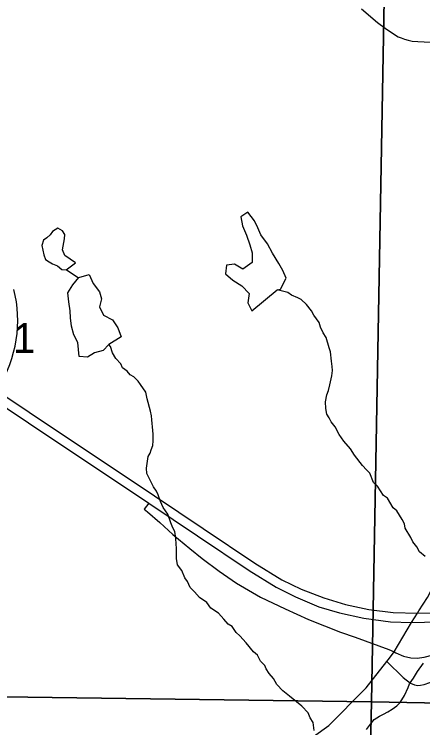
# Model space of a CAD drawing. Extents: x 0 to 34, y 0 to 22.
# Drawn here: x 3.401 to 3.978, y 16.77 to 17.776 of the extents above; entities that cross this region are included whole.
import ezdxf

# ---------------------------------------------------------------- set-up
doc = ezdxf.new("R2010")
doc.units = 0
for name, color, linetype in [('GM_X_County_Road', 7, 'Continuous'), ('GM_X_Interchange_Ramps', 7, 'Continuous'), ('GM_X_Interstate_Route', 7, 'Continuous'), ('GM_X_Interstate_Shield', 7, 'Continuous'), ('GM_X_Minor_Lake', 7, 'Continuous'), ('GM_X_Minor_River', 7, 'Continuous'), ('GM_X_Section', 7, 'Continuous'), ('GM_X_Section_Text', 7, 'Continuous'), ('GM_X_State_Route', 7, 'Continuous'), ('GM_X_Township_Road', 7, 'Continuous'), ('GM_X_US_Route', 7, 'Continuous')]:
    doc.layers.add(name, color=color, linetype=linetype)

msp = doc.modelspace()

# ---------------------------------------------------------------- linework, layer by layer
at = {"layer": 'GM_X_County_Road'}
msp.add_lwpolyline([(3.891, 17.7836), (3.9137, 17.7643), (3.9245, 17.756), (3.9335, 17.7499), (3.9431, 17.7441), (3.947, 17.7425), (3.9517, 17.7407), (3.9569, 17.7392), (3.9628, 17.738), (3.9706, 17.7373), (3.9979, 17.7358)], dxfattribs=at)
at = {"layer": 'GM_X_Interchange_Ramps'}
for points in [[(3.5913, 17.0864), (3.5849, 17.0781), (3.5894, 17.0742), (3.6067, 17.0592), (3.6253, 17.0424), (3.6492, 17.0225), (3.6666, 17.0086), (3.6904, 16.9908), (3.7151, 16.9737), (3.7489, 16.954), (3.7836, 16.9377), (3.8166, 16.9228), (3.8614, 16.905), (3.8821, 16.8975)], [(3.9374, 16.8771), (3.9398, 16.8758), (3.9505, 16.8707), (3.9607, 16.8684), (3.9698, 16.8683), (3.9796, 16.8695), (3.9921, 16.8727), (4.0041, 16.8782), (4.0566, 16.9039), (4.1192, 16.9366), (4.1254, 16.9397), (4.1215, 16.9477)], [(3.8821, 16.8975), (3.9296, 16.8803), (3.9374, 16.8771)]]:
    msp.add_lwpolyline(points, dxfattribs=at)
at = {"layer": 'GM_X_Interstate_Route'}
for points in [[(2.8343, 17.6093), (3.4225, 17.2149), (3.5995, 17.097), (3.6679, 17.051), (3.741, 17.0021), (3.7789, 16.9786), (3.8063, 16.9653), (3.8379, 16.9533), (3.8686, 16.9439), (3.9015, 16.9368), (3.936, 16.9325), (3.9703, 16.9317), (3.9919, 16.9322), (4.0072, 16.9333), (4.0421, 16.9388), (4.0807, 16.9496), (4.1185, 16.9639), (4.1778, 16.99), (4.2466, 17.0247)], [(3.0829, 17.427), (3.4215, 17.1997), (3.5913, 17.0864)], [(3.5913, 17.0864), (3.6597, 17.0405), (3.7327, 16.9916), (3.7707, 16.9681), (3.7981, 16.9547), (3.8312, 16.9407), (3.8604, 16.9319), (3.8946, 16.9245), (3.9319, 16.9192), (3.9616, 16.9183), (3.9985, 16.9192), (4.0407, 16.9251), (4.0872, 16.9354), (4.1215, 16.9477)]]:
    msp.add_lwpolyline(points, dxfattribs=at)
at = {"layer": 'GM_X_Interstate_Shield'}
msp.add_arc((3.2288, 17.3445), 0.1776, 281.537, 14.1934, dxfattribs=at)
at = {"layer": 'GM_X_Minor_Lake'}
msp.add_line((3.7366, 17.3579), (3.7725, 17.3873), dxfattribs=at)
for points in [[(3.7725, 17.3873), (3.7769, 17.3883), (3.7849, 17.4037), (3.7803, 17.4145), (3.7748, 17.4245), (3.7657, 17.4392), (3.7588, 17.4523), (3.7493, 17.4651), (3.745, 17.4747), (3.7403, 17.4847), (3.7311, 17.4967), (3.7211, 17.4901), (3.7234, 17.4775), (3.7288, 17.4645), (3.7337, 17.4507), (3.7372, 17.4395), (3.7369, 17.4259), (3.7237, 17.4163), (3.7121, 17.4235), (3.701, 17.4223), (3.6996, 17.4098), (3.7096, 17.4011), (3.7223, 17.3932), (3.7327, 17.3823), (3.7308, 17.369), (3.7366, 17.3579)], [(3.4748, 17.4157), (3.488, 17.4252), (3.473, 17.4359), (3.4694, 17.4436), (3.4725, 17.4591), (3.4727, 17.4655), (3.4694, 17.4706), (3.4627, 17.4745), (3.4553, 17.4698), (3.4522, 17.4649), (3.4475, 17.4605), (3.4428, 17.4576), (3.4404, 17.45), (3.443, 17.4367), (3.4455, 17.4301), (3.4508, 17.4266), (3.4556, 17.4242), (3.4624, 17.4213)], [(3.4624, 17.4213), (3.4687, 17.4159), (3.4748, 17.4157)], [(3.5347, 17.3105), (3.5269, 17.3018), (3.5146, 17.2987), (3.505, 17.2925), (3.4932, 17.2936), (3.4919, 17.3031), (3.4911, 17.313), (3.4857, 17.3238), (3.4822, 17.3361), (3.481, 17.3479), (3.4801, 17.3578), (3.4785, 17.3704), (3.477, 17.3833), (3.4841, 17.3942), (3.4927, 17.4046), (3.5073, 17.4091), (3.5126, 17.3961), (3.5218, 17.3844), (3.5246, 17.3745), (3.5217, 17.3632), (3.5274, 17.3516), (3.5398, 17.3452), (3.5475, 17.3336)], [(3.5475, 17.3336), (3.5523, 17.3211), (3.5347, 17.3105)]]:
    msp.add_lwpolyline(points, dxfattribs=at)
at = {"layer": 'GM_X_Minor_River'}
for points in [[(3.4921, 17.4039), (3.4748, 17.4157)], [(3.9812, 17.0112), (3.9731, 17.0179), (3.9692, 17.0249), (3.9637, 17.0319), (3.9609, 17.0381), (3.953, 17.0516), (3.9517, 17.0574), (3.9485, 17.0636), (3.9413, 17.0756), (3.9361, 17.08), (3.9279, 17.0935), (3.9223, 17.0972), (3.9137, 17.1108), (3.9081, 17.1159), (3.9029, 17.129), (3.8981, 17.1337), (3.8926, 17.1396), (3.8814, 17.1544), (3.8756, 17.163), (3.8661, 17.174), (3.8596, 17.1833), (3.8543, 17.1941), (3.8484, 17.2012), (3.8456, 17.207), (3.8424, 17.212), (3.8411, 17.22), (3.8403, 17.2296), (3.8422, 17.2394), (3.8447, 17.2454), (3.8464, 17.2533), (3.8495, 17.2661), (3.8502, 17.2737), (3.85, 17.2794), (3.8488, 17.287), (3.8473, 17.3), (3.8456, 17.3054), (3.8412, 17.32), (3.8372, 17.3266), (3.8333, 17.3347), (3.8313, 17.3412), (3.824, 17.3517), (3.8208, 17.3579), (3.8135, 17.3665), (3.8062, 17.3736), (3.8013, 17.3761), (3.7927, 17.3798), (3.7872, 17.3834), (3.7725, 17.3873)], [(3.8247, 16.7662), (3.8232, 16.7776), (3.8189, 16.7842), (3.8161, 16.7912), (3.8073, 16.8006), (3.7899, 16.8145), (3.7803, 16.822), (3.7719, 16.8311), (3.7673, 16.8396), (3.761, 16.8466), (3.7567, 16.8529), (3.755, 16.8579), (3.7487, 16.8641), (3.7445, 16.8723), (3.7389, 16.877), (3.7287, 16.8899), (3.7196, 16.8994), (3.7144, 16.9045), (3.7086, 16.9126), (3.7034, 16.9159), (3.6972, 16.9233), (3.6896, 16.9315), (3.6788, 16.9388), (3.673, 16.9466), (3.6626, 16.9538), (3.6557, 16.9616), (3.6498, 16.9679), (3.6459, 16.9764), (3.6419, 16.9814), (3.6377, 16.9918), (3.6315, 16.9997), (3.6303, 17.0088), (3.6302, 17.0168), (3.6304, 17.0225), (3.6299, 17.0294), (3.6294, 17.037), (3.6278, 17.0465), (3.625, 17.0519), (3.6222, 17.0589), (3.6181, 17.0712), (3.6115, 17.0805), (3.6077, 17.089), (3.6046, 17.0986), (3.6021, 17.1037), (3.5977, 17.1095), (3.5924, 17.1211), (3.5885, 17.1284), (3.588, 17.1361), (3.5901, 17.1523), (3.5933, 17.1572), (3.5946, 17.162), (3.5967, 17.1677), (3.5973, 17.1745), (3.5973, 17.184), (3.5971, 17.1889), (3.5953, 17.2042), (3.5951, 17.2095), (3.5938, 17.2164), (3.5891, 17.2337), (3.5872, 17.2429), (3.5796, 17.2538), (3.5763, 17.2588), (3.5701, 17.2647), (3.5648, 17.2676), (3.5608, 17.2727), (3.5542, 17.2774), (3.5517, 17.2829), (3.5448, 17.2907), (3.5401, 17.2985), (3.537, 17.3073), (3.5347, 17.3105)], [(3.8984, 16.7674), (3.904, 16.7752), (3.9091, 16.7815), (3.9165, 16.7862), (3.9223, 16.789), (3.9285, 16.7926), (3.9343, 16.7962), (3.9413, 16.8009), (3.946, 16.8057), (3.9517, 16.8157), (3.957, 16.8269), (3.9587, 16.8318), (3.9647, 16.84), (3.97, 16.8493), (3.9787, 16.8612)]]:
    msp.add_lwpolyline(points, dxfattribs=at)
at = {"layer": 'GM_X_Section'}
for points in [[(3.923, 17.7965), (3.9054, 16.8066), (2.9007, 16.8204), (2.9334, 17.8114)], [(3.9054, 16.8066), (4.328, 16.7986), (4.3256, 16.7771), (4.3103, 16.7385), (4.3, 16.7205), (4.2802, 16.7024), (4.2517, 16.6823), (4.2355, 16.6713), (4.2093, 16.6549), (4.1675, 16.6328), (4.1258, 16.6145), (4.0845, 16.5985), (4.0692, 16.5947), (4.0556, 16.5931), (4.0495, 16.5944), (4.0387, 16.6015), (4.0223, 16.614), (4.0029, 16.6235), (3.9905, 16.6288), (3.9622, 16.6321), (3.9299, 16.6291), (3.9079, 16.6163), (3.9011, 16.6124)]]:
    msp.add_lwpolyline(points, close=True, dxfattribs=at)
for points in [[(4.328, 16.7986), (3.9054, 16.8066), (3.923, 17.7965)], [(2.9007, 16.8204), (3.9054, 16.8066), (3.9011, 16.6124), (3.88, 16.6356), (3.8496, 16.6451), (3.806, 16.6427), (3.7481, 16.632), (3.6889, 16.6111), (3.6323, 16.5909), (3.6125, 16.5868), (3.5393, 16.5662), (3.511, 16.5548), (3.4795, 16.5389), (3.4415, 16.5156), (3.3921, 16.48)]]:
    msp.add_lwpolyline(points, dxfattribs=at)
at = {"layer": 'GM_X_State_Route'}
for points in [[(3.9723, 16.935), (3.9843, 16.9535), (4.0117, 17.0063), (4.014, 17.0106)], [(3.9305, 16.8679), (3.9374, 16.8771), (3.9616, 16.9183), (3.9703, 16.9317), (3.9723, 16.935)], [(3.8957, 16.8243), (3.8979, 16.8264), (3.9271, 16.8633), (3.9305, 16.8679)], [(3.3641, 16.6318), (3.4249, 16.631), (3.4707, 16.6328), (3.5386, 16.6413), (3.6368, 16.6627), (3.6902, 16.6809), (3.7376, 16.7017), (3.7768, 16.7241), (3.8451, 16.7734), (3.8957, 16.8243)]]:
    msp.add_lwpolyline(points, dxfattribs=at)
at = {"layer": 'GM_X_Township_Road'}
msp.add_lwpolyline([(3.9271, 16.8633), (3.9501, 16.8407), (3.9604, 16.8329), (3.9658, 16.8304), (3.9706, 16.8295), (3.9743, 16.8299), (3.9798, 16.8311), (3.9875, 16.834), (3.9999, 16.8411), (4.0333, 16.8691), (4.0411, 16.8754), (4.0522, 16.8808), (4.1885, 16.9494)], dxfattribs=at)
at = {"layer": 'GM_X_US_Route'}
for points in [[(3.0829, 17.427), (3.4215, 17.1997), (3.5913, 17.0864)], [(3.5913, 17.0864), (3.6597, 17.0405), (3.7327, 16.9916), (3.7707, 16.9681), (3.7981, 16.9547), (3.8312, 16.9407), (3.8604, 16.9319), (3.8946, 16.9245), (3.9319, 16.9192), (3.9616, 16.9183), (3.9985, 16.9192), (4.0407, 16.9251), (4.0872, 16.9354), (4.1215, 16.9477)]]:
    msp.add_lwpolyline(points, dxfattribs=at)

# ---------------------------------------------------------------- texts
at = {"layer": 'GM_X_Section_Text'}
msp.add_text('1', height=0.0419, rotation=0, dxfattribs=at).set_placement((3.3998, 17.2985))

doc.saveas('drawing.dxf')
